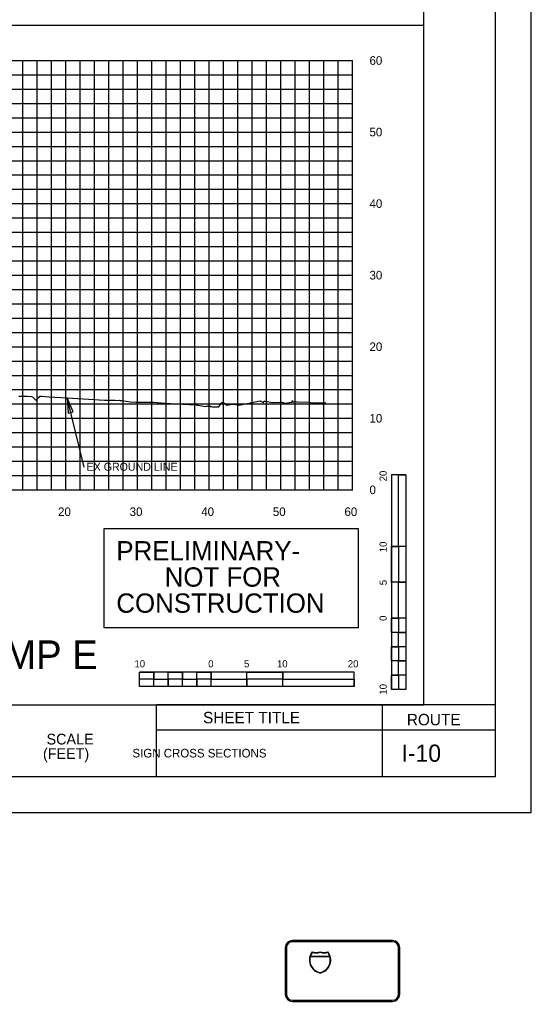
# Model space of a CAD drawing. Extents: x 1797809 to 2198143, y 249608 to 1237864.
# Drawn here: x 2195126.4 to 2195197.9, y 1237091.6 to 1237228.8 of the extents above; entities that cross this region are included whole.
import ezdxf

# ---------------------------------------------------------------- set-up
doc = ezdxf.new("R2010")
doc.units = 0
for name, color, linetype in [('10', 7, 'Continuous'), ('29', 7, 'Continuous'), ('3', 7, 'Continuous'), ('31', 7, 'Continuous'), ('60', 7, 'Continuous'), ('DESIGN - SHEET - Light Grid', 7, 'Continuous'), ('GSCOLORFILL', 7, 'Continuous'), ('GSDIMS', 7, 'Continuous'), ('GSOUTLINE', 7, 'Continuous'), ('GSSHT', 7, 'Continuous'), ('Level 1', 7, 'Continuous'), ('Level 30', 7, 'Continuous'), ('Level 33', 7, 'Continuous'), ('Level 45', 7, 'Continuous'), ('Level 55', 7, 'Continuous'), ('UGUT', 7, 'Continuous')]:
    doc.layers.add(name, color=color, linetype=linetype)

msp = doc.modelspace()

# ---------------------------------------------------------------- linework, layer by layer
at = {"layer": '29'}
for p, q in [((2195178.33, 1237165.19), (2195178.33, 1237135.19)), ((2195180.33, 1237165.19), (2195178.33, 1237165.19)), ((2195178.33, 1237165.19), (2195178.33, 1237135.19)), ((2195180.33, 1237165.19), (2195178.33, 1237165.19)), ((2195180.33, 1237165.19), (2195180.33, 1237155.19)), ((2195180.33, 1237165.19), (2195180.33, 1237135.19)), ((2195180.33, 1237165.19), (2195180.33, 1237155.19)), ((2195180.33, 1237165.19), (2195180.33, 1237135.19)), ((2195179.33, 1237155.19), (2195178.33, 1237155.19)), ((2195180.33, 1237155.19), (2195178.33, 1237155.19)), ((2195179.33, 1237155.19), (2195178.33, 1237155.19)), ((2195180.33, 1237155.19), (2195178.33, 1237155.19)), ((2195179.33, 1237155.19), (2195179.33, 1237150.19)), ((2195179.33, 1237155.19), (2195179.33, 1237150.19)), ((2195180.33, 1237150.19), (2195178.33, 1237150.19)), ((2195180.33, 1237150.19), (2195178.33, 1237150.19)), ((2195180.33, 1237150.19), (2195179.33, 1237150.19)), ((2195180.33, 1237150.19), (2195179.33, 1237150.19)), ((2195180.33, 1237150.19), (2195180.33, 1237145.19)), ((2195180.33, 1237150.19), (2195180.33, 1237145.19)), ((2195179.33, 1237145.19), (2195178.33, 1237145.19)), ((2195180.33, 1237145.19), (2195178.33, 1237145.19)), ((2195179.33, 1237145.19), (2195178.33, 1237145.19)), ((2195180.33, 1237145.19), (2195178.33, 1237145.19)), ((2195179.33, 1237145.19), (2195179.33, 1237143.19)), ((2195179.33, 1237145.19), (2195179.33, 1237143.19)), ((2195180.33, 1237143.19), (2195179.33, 1237143.19)), ((2195180.33, 1237143.19), (2195179.33, 1237143.19)), ((2195180.33, 1237143.19), (2195180.33, 1237141.19)), ((2195180.33, 1237143.19), (2195180.33, 1237141.19)), ((2195179.33, 1237141.19), (2195178.33, 1237141.19)), ((2195179.33, 1237141.19), (2195178.33, 1237141.19)), ((2195179.33, 1237141.19), (2195179.33, 1237139.19)), ((2195179.33, 1237141.19), (2195179.33, 1237139.19)), ((2195180.33, 1237139.19), (2195179.33, 1237139.19)), ((2195180.33, 1237139.19), (2195179.33, 1237139.19)), ((2195180.33, 1237139.19), (2195180.33, 1237137.19)), ((2195180.33, 1237139.19), (2195180.33, 1237137.19)), ((2195173.13, 1237137.63), (2195143.13, 1237137.63)), ((2195143.13, 1237135.63), (2195143.13, 1237137.63)), ((2195173.13, 1237137.63), (2195143.13, 1237137.63)), ((2195143.13, 1237135.63), (2195143.13, 1237137.63)), ((2195145.13, 1237136.63), (2195145.13, 1237137.63)), ((2195145.13, 1237136.63), (2195145.13, 1237137.63)), ((2195149.13, 1237136.63), (2195149.13, 1237137.63)), ((2195149.13, 1237136.63), (2195149.13, 1237137.63)), ((2195153.13, 1237136.63), (2195153.13, 1237137.63)), ((2195153.13, 1237135.63), (2195153.13, 1237137.63)), ((2195153.13, 1237136.63), (2195153.13, 1237137.63)), ((2195153.13, 1237135.63), (2195153.13, 1237137.63)), ((2195158.13, 1237135.63), (2195158.13, 1237137.63)), ((2195158.13, 1237135.63), (2195158.13, 1237137.63)), ((2195163.13, 1237136.63), (2195163.13, 1237137.63)), ((2195163.13, 1237135.63), (2195163.13, 1237137.63)), ((2195163.13, 1237136.63), (2195163.13, 1237137.63)), ((2195163.13, 1237135.63), (2195163.13, 1237137.63)), ((2195173.13, 1237135.63), (2195173.13, 1237137.63)), ((2195173.13, 1237135.63), (2195173.13, 1237137.63)), ((2195145.13, 1237136.63), (2195143.13, 1237136.63)), ((2195145.13, 1237136.63), (2195143.13, 1237136.63)), ((2195147.13, 1237135.63), (2195147.13, 1237136.63)), ((2195149.13, 1237136.63), (2195147.13, 1237136.63)), ((2195147.13, 1237135.63), (2195147.13, 1237136.63)), ((2195149.13, 1237136.63), (2195147.13, 1237136.63)), ((2195151.13, 1237135.63), (2195151.13, 1237136.63)), ((2195153.13, 1237136.63), (2195151.13, 1237136.63)), ((2195151.13, 1237135.63), (2195151.13, 1237136.63)), ((2195153.13, 1237136.63), (2195151.13, 1237136.63)), ((2195158.13, 1237135.63), (2195158.13, 1237136.63)), ((2195163.13, 1237136.63), (2195158.13, 1237136.63)), ((2195158.13, 1237135.63), (2195158.13, 1237136.63)), ((2195163.13, 1237136.63), (2195158.13, 1237136.63)), ((2195179.33, 1237137.19), (2195178.33, 1237137.19)), ((2195179.33, 1237137.19), (2195178.33, 1237137.19)), ((2195179.33, 1237137.19), (2195179.33, 1237135.19)), ((2195179.33, 1237137.19), (2195179.33, 1237135.19)), ((2195173.13, 1237135.63), (2195143.13, 1237135.63)), ((2195173.13, 1237135.63), (2195143.13, 1237135.63)), ((2195147.13, 1237135.63), (2195145.13, 1237135.63)), ((2195147.13, 1237135.63), (2195145.13, 1237135.63)), ((2195151.13, 1237135.63), (2195149.13, 1237135.63)), ((2195151.13, 1237135.63), (2195149.13, 1237135.63)), ((2195158.13, 1237135.63), (2195153.13, 1237135.63)), ((2195158.13, 1237135.63), (2195153.13, 1237135.63)), ((2195173.13, 1237135.63), (2195163.13, 1237135.63)), ((2195173.13, 1237135.63), (2195163.13, 1237135.63)), ((2195180.33, 1237135.19), (2195178.33, 1237135.19)), ((2195180.33, 1237135.19), (2195178.33, 1237135.19))]:
    msp.add_line(p, q, dxfattribs=at)
for points in [[(2195179.33, 1237155.19), (2195179.33, 1237165.19), (2195180.33, 1237165.19), (2195180.33, 1237155.19)], [(2195179.33, 1237155.19), (2195179.33, 1237165.19), (2195180.33, 1237165.19), (2195180.33, 1237155.19)], [(2195178.33, 1237150.19), (2195178.33, 1237155.19), (2195179.33, 1237155.19), (2195179.33, 1237150.19)], [(2195178.33, 1237150.19), (2195178.33, 1237155.19), (2195179.33, 1237155.19), (2195179.33, 1237150.19)], [(2195179.33, 1237145.19), (2195179.33, 1237150.19), (2195180.33, 1237150.19), (2195180.33, 1237145.19)], [(2195179.33, 1237145.19), (2195179.33, 1237150.19), (2195180.33, 1237150.19), (2195180.33, 1237145.19)], [(2195178.33, 1237143.19), (2195178.33, 1237145.19), (2195179.33, 1237145.19), (2195179.33, 1237143.19)], [(2195178.33, 1237143.19), (2195178.33, 1237145.19), (2195179.33, 1237145.19), (2195179.33, 1237143.19)], [(2195179.33, 1237141.19), (2195179.33, 1237143.19), (2195180.33, 1237143.19), (2195180.33, 1237141.19)], [(2195179.33, 1237141.19), (2195179.33, 1237143.19), (2195180.33, 1237143.19), (2195180.33, 1237141.19)], [(2195178.33, 1237139.19), (2195178.33, 1237141.19), (2195179.33, 1237141.19), (2195179.33, 1237139.19)], [(2195178.33, 1237139.19), (2195178.33, 1237141.19), (2195179.33, 1237141.19), (2195179.33, 1237139.19)], [(2195179.33, 1237137.19), (2195179.33, 1237139.19), (2195180.33, 1237139.19), (2195180.33, 1237137.19)], [(2195179.33, 1237137.19), (2195179.33, 1237139.19), (2195180.33, 1237139.19), (2195180.33, 1237137.19)], [(2195143.13, 1237137.63), (2195145.13, 1237137.63), (2195145.13, 1237136.63), (2195143.13, 1237136.63)], [(2195143.13, 1237137.63), (2195145.13, 1237137.63), (2195145.13, 1237136.63), (2195143.13, 1237136.63)], [(2195147.13, 1237137.63), (2195149.13, 1237137.63), (2195149.13, 1237136.63), (2195147.13, 1237136.63)], [(2195147.13, 1237137.63), (2195149.13, 1237137.63), (2195149.13, 1237136.63), (2195147.13, 1237136.63)], [(2195151.13, 1237137.63), (2195153.13, 1237137.63), (2195153.13, 1237136.63), (2195151.13, 1237136.63)], [(2195151.13, 1237137.63), (2195153.13, 1237137.63), (2195153.13, 1237136.63), (2195151.13, 1237136.63)], [(2195158.13, 1237137.63), (2195163.13, 1237137.63), (2195163.13, 1237136.63), (2195158.13, 1237136.63)], [(2195158.13, 1237137.63), (2195163.13, 1237137.63), (2195163.13, 1237136.63), (2195158.13, 1237136.63)], [(2195145.13, 1237136.63), (2195147.13, 1237136.63), (2195147.13, 1237135.63), (2195145.13, 1237135.63)], [(2195145.13, 1237136.63), (2195147.13, 1237136.63), (2195147.13, 1237135.63), (2195145.13, 1237135.63)], [(2195149.13, 1237136.63), (2195151.13, 1237136.63), (2195151.13, 1237135.63), (2195149.13, 1237135.63)], [(2195149.13, 1237136.63), (2195151.13, 1237136.63), (2195151.13, 1237135.63), (2195149.13, 1237135.63)], [(2195153.13, 1237136.63), (2195158.13, 1237136.63), (2195158.13, 1237135.63), (2195153.13, 1237135.63)], [(2195153.13, 1237136.63), (2195158.13, 1237136.63), (2195158.13, 1237135.63), (2195153.13, 1237135.63)], [(2195163.13, 1237136.63), (2195173.13, 1237136.63), (2195173.13, 1237135.63), (2195163.13, 1237135.63)], [(2195163.13, 1237136.63), (2195173.13, 1237136.63), (2195173.13, 1237135.63), (2195163.13, 1237135.63)], [(2195178.33, 1237135.19), (2195178.33, 1237137.19), (2195179.33, 1237137.19), (2195179.33, 1237135.19)], [(2195178.33, 1237135.19), (2195178.33, 1237137.19), (2195179.33, 1237137.19), (2195179.33, 1237135.19)]]:
    msp.add_lwpolyline(points, close=True, dxfattribs=at)
at = {"layer": '3'}
for p, q in [((2194882.86, 1237228.05), (2195182.86, 1237228.05)), ((2195135.41, 1237166.27), (2195133.01, 1237175.96))]:
    msp.add_line(p, q, dxfattribs=at)
at = {"layer": '60'}
for p, q in [((2195172.86, 1237163.11), (2195172.86, 1237223.11)), ((2195172.92, 1237203.11), (2195172.86, 1237203.11)), ((2195172.92, 1237193.11), (2195172.86, 1237193.11)), ((2195172.92, 1237183.11), (2195172.86, 1237183.11)), ((2195172.92, 1237173.11), (2195172.86, 1237173.11)), ((2195042.86, 1237163.11), (2195172.86, 1237163.11)), ((2195132.86, 1237163.05), (2195132.86, 1237163.11)), ((2195142.86, 1237163.05), (2195142.86, 1237163.11)), ((2195152.86, 1237163.05), (2195152.86, 1237163.11)), ((2195162.86, 1237163.05), (2195162.86, 1237163.11)), ((2195172.86, 1237163.05), (2195172.86, 1237163.11)), ((2195172.92, 1237163.11), (2195172.86, 1237163.11))]:
    msp.add_line(p, q, dxfattribs=at)
at = {"layer": 'DESIGN - SHEET - Light Grid'}
msp.add_lwpolyline([(2195126.28, 1237176.21), (2195126.62, 1237176.21), (2195127.09, 1237176.21), (2195127.33, 1237176.21), (2195127.45, 1237176.21), (2195128.07, 1237176.14), (2195128.17, 1237176.09), (2195128.27, 1237176.03), (2195128.58, 1237175.72), (2195128.62, 1237175.71), (2195128.72, 1237175.64), (2195129.14, 1237176.06), (2195129.23, 1237176.21), (2195129.43, 1237176.21), (2195130.49, 1237176.12), (2195133.01, 1237175.96), (2195138.24, 1237175.63), (2195139.73, 1237175.64), (2195140.21, 1237175.61), (2195140.34, 1237175.63), (2195140.42, 1237175.6), (2195140.68, 1237175.61), (2195141.9, 1237175.42), (2195142.61, 1237175.38), (2195144.95, 1237175.38), (2195145.08, 1237175.38), (2195146.11, 1237175.26), (2195148.21, 1237175.13), (2195151.01, 1237174.97), (2195152.39, 1237174.77), (2195152.64, 1237174.87), (2195152.66, 1237174.78), (2195152.91, 1237174.82), (2195152.93, 1237174.91), (2195152.99, 1237174.78), (2195153, 1237174.77), (2195153.02, 1237174.75), (2195153.07, 1237174.76), (2195153.21, 1237174.75), (2195153.31, 1237174.73), (2195153.59, 1237174.71), (2195153.95, 1237174.69), (2195154.21, 1237174.71), (2195154.23, 1237174.72), (2195154.52, 1237175.22), (2195154.72, 1237175.38), (2195154.76, 1237175.17), (2195154.8, 1237175.34), (2195155.34, 1237174.94), (2195155.41, 1237174.96), (2195155.5, 1237174.99), (2195155.8, 1237175.03), (2195156.34, 1237175.07), (2195157.02, 1237174.92), (2195159.99, 1237175.57), (2195160.47, 1237175.3), (2195160.52, 1237175.44), (2195160.59, 1237175.49), (2195160.7, 1237175.51), (2195161.77, 1237175.32), (2195162.72, 1237175.38), (2195162.85, 1237175.37), (2195163.03, 1237175.34), (2195163.46, 1237175.24), (2195164.39, 1237175.35), (2195164.52, 1237175.58), (2195164.53, 1237175.4), (2195164.54, 1237175.34), (2195164.91, 1237175.46), (2195165.06, 1237175.41), (2195166.86, 1237175.37), (2195167.27, 1237175.27), (2195169.17, 1237175.26)], dxfattribs=at)
at = {"layer": 'GSCOLORFILL'}
for p, q in [((2195145.52, 1237123.04), (2195145.52, 1237133.05)), ((2195177.05, 1237123.04), (2195177.05, 1237133.05))]:
    msp.add_line(p, q, dxfattribs=at)
msp.add_lwpolyline([(2194870.36, 1237123.04), (2195192.86, 1237123.04), (2195192.86, 1237333.04), (2194870.36, 1237333.04)], close=True, dxfattribs=at)
at = {"layer": 'GSDIMS'}
msp.add_lwpolyline([(2195133.01, 1237175.96), (2195133.18, 1237173.82), (2195133.86, 1237174.01)], close=True, dxfattribs=at)
at = {"layer": 'GSOUTLINE'}
for p, q in [((2195145.52, 1237129.57), (2195177.05, 1237129.57)), ((2195177.05, 1237129.57), (2195192.86, 1237129.57)), ((2195163.49, 1237099.12), (2195163.49, 1237092.62)), ((2195163.65, 1237099.12), (2195163.65, 1237092.62)), ((2195178.48, 1237100.12), (2195164.49, 1237100.12)), ((2195178.48, 1237099.95), (2195164.49, 1237099.95)), ((2195179.32, 1237092.62), (2195179.32, 1237099.12)), ((2195179.48, 1237092.62), (2195179.48, 1237099.12)), ((2195164.49, 1237091.79), (2195178.48, 1237091.79)), ((2195164.49, 1237091.62), (2195178.48, 1237091.62))]:
    msp.add_line(p, q, dxfattribs=at)
for points in [[(2195169.73, 1237097.87), (2195166.99, 1237097.87)], [(2195167, 1237097.93), (2195169.71, 1237097.93)]]:
    msp.add_lwpolyline(points, dxfattribs=at)
for centre, major_axis, ratio, start_param, end_param in [((2195164.49, 1237099.12), (1, 0), 0.999829, 1.570796, 3.141593), ((2195164.49, 1237099.12), (0.833, 0), 0.999829, 1.570796, 3.141593), ((2195178.48, 1237099.12), (1, 0), 0.999829, 0, 1.570796), ((2195178.48, 1237099.12), (0.833, 0), 0.999829, 0, 1.570796), ((2195168.73, 1237097.4), (1.87, 0), 0.997059, 2.472588, 4.511032), ((2195168.73, 1237097.4), (1.81, 0), 0.997059, 2.876207, 4.503988), ((2195168.73, 1237097.4), (1.81, 0), 0.997059, 2.495747, 2.84029), ((2195167.81, 1237100.34), (1.87, 0), 0.997059, 4.415842, 5.008936), ((2195167.81, 1237100.34), (1.94, 0), 0.997059, 4.438241, 4.999094), ((2195168.91, 1237100.34), (1.87, 0), 0.997059, 4.415842, 5.008936), ((2195167.98, 1237097.4), (1.87, 0), 0.997059, 4.913746, 6.95219), ((2195168.91, 1237100.34), (1.94, 0), 0.997059, 4.425684, 4.986537), ((2195167.98, 1237097.4), (1.81, 0), 0.997059, 4.92079, 6.548571), ((2195167.98, 1237097.4), (1.81, 0), 0.997059, 0.301302, 0.645846), ((2195164.49, 1237092.62), (1, 0), 0.999829, 3.141593, 4.712389), ((2195164.49, 1237092.62), (0.833, 0), 0.999829, 3.141593, 4.712389), ((2195178.48, 1237092.62), (1, 0), 0.999829, 4.712389, 6.283185), ((2195178.48, 1237092.62), (0.833, 0), 0.999829, 4.712389, 6.283185)]:
    msp.add_ellipse(centre, major_axis=major_axis, ratio=ratio, start_param=start_param, end_param=end_param, dxfattribs=at)
at = {"layer": 'GSSHT'}
for p, q in [((2195042.86, 1237223.11), (2195172.86, 1237223.11)), ((2195126.86, 1237163.11), (2195126.86, 1237223.11)), ((2195128.86, 1237163.11), (2195128.86, 1237223.11)), ((2195130.86, 1237163.11), (2195130.86, 1237223.11)), ((2195132.86, 1237163.11), (2195132.86, 1237223.11)), ((2195134.86, 1237163.11), (2195134.86, 1237223.11)), ((2195136.86, 1237163.11), (2195136.86, 1237223.11)), ((2195138.86, 1237163.11), (2195138.86, 1237223.11)), ((2195140.86, 1237163.11), (2195140.86, 1237223.11)), ((2195142.86, 1237163.11), (2195142.86, 1237223.11)), ((2195144.86, 1237163.11), (2195144.86, 1237223.11)), ((2195146.86, 1237163.11), (2195146.86, 1237223.11)), ((2195148.86, 1237163.11), (2195148.86, 1237223.11)), ((2195150.86, 1237163.11), (2195150.86, 1237223.11)), ((2195152.86, 1237163.11), (2195152.86, 1237223.11)), ((2195154.86, 1237163.11), (2195154.86, 1237223.11)), ((2195156.86, 1237163.11), (2195156.86, 1237223.11)), ((2195158.86, 1237163.11), (2195158.86, 1237223.11)), ((2195160.86, 1237163.11), (2195160.86, 1237223.11)), ((2195162.86, 1237163.11), (2195162.86, 1237223.11)), ((2195164.86, 1237163.11), (2195164.86, 1237223.11)), ((2195166.86, 1237163.11), (2195166.86, 1237223.11)), ((2195168.86, 1237163.11), (2195168.86, 1237223.11)), ((2195170.86, 1237163.11), (2195170.86, 1237223.11)), ((2195172.86, 1237163.11), (2195172.86, 1237223.11)), ((2195042.86, 1237221.11), (2195172.86, 1237221.11)), ((2195042.86, 1237219.11), (2195172.86, 1237219.11)), ((2195042.86, 1237217.11), (2195172.86, 1237217.11)), ((2195042.86, 1237215.11), (2195172.86, 1237215.11)), ((2195042.86, 1237213.11), (2195172.86, 1237213.11)), ((2195042.86, 1237211.11), (2195172.86, 1237211.11)), ((2195042.86, 1237209.11), (2195172.86, 1237209.11)), ((2195042.86, 1237207.11), (2195172.86, 1237207.11)), ((2195042.86, 1237205.11), (2195172.86, 1237205.11)), ((2195042.86, 1237203.11), (2195172.86, 1237203.11)), ((2195042.86, 1237201.11), (2195172.86, 1237201.11)), ((2195042.86, 1237199.11), (2195172.86, 1237199.11)), ((2195042.86, 1237197.11), (2195172.86, 1237197.11)), ((2195042.86, 1237195.11), (2195172.86, 1237195.11)), ((2195042.86, 1237193.11), (2195172.86, 1237193.11)), ((2195042.86, 1237191.11), (2195172.86, 1237191.11)), ((2195042.86, 1237189.11), (2195172.86, 1237189.11)), ((2195042.86, 1237187.11), (2195172.86, 1237187.11)), ((2195042.86, 1237185.11), (2195172.86, 1237185.11)), ((2195042.86, 1237183.11), (2195172.86, 1237183.11)), ((2195042.86, 1237181.11), (2195172.86, 1237181.11)), ((2195042.86, 1237179.11), (2195172.86, 1237179.11)), ((2195042.86, 1237177.11), (2195172.86, 1237177.11)), ((2195042.86, 1237175.11), (2195172.86, 1237175.11)), ((2195042.86, 1237173.11), (2195172.86, 1237173.11)), ((2195042.86, 1237171.11), (2195172.86, 1237171.11)), ((2195042.86, 1237169.11), (2195172.86, 1237169.11)), ((2195042.86, 1237167.11), (2195172.86, 1237167.11)), ((2195042.86, 1237165.11), (2195172.86, 1237165.11)), ((2195042.86, 1237163.11), (2195172.86, 1237163.11))]:
    msp.add_line(p, q, dxfattribs=at)
msp.add_lwpolyline([(2194857.86, 1237118.04), (2195197.86, 1237118.04), (2195197.86, 1237338.04), (2194857.86, 1237338.04)], close=True, dxfattribs=at)
at = {"layer": 'Level 30'}
msp.add_lwpolyline([(2195138.22, 1237157.72), (2195173.68, 1237157.72), (2195173.68, 1237143.82), (2195138.22, 1237143.82)], close=True, dxfattribs=at)
at = {"layer": 'Level 45'}
msp.add_lwpolyline([(2194882.86, 1237133.05), (2195182.86, 1237133.05), (2195182.86, 1237323.05), (2194882.86, 1237323.05)], close=True, dxfattribs=at)
at = {"layer": 'UGUT'}
msp.add_line((2195192.86, 1237133.05), (2195145.52, 1237133.05), dxfattribs=at)

# ---------------------------------------------------------------- texts
at = {"layer": '10'}
for s, p in [('20', (2195131.76, 1237159.45)), ('30', (2195141.76, 1237159.45)), ('40', (2195151.76, 1237159.45)), ('50', (2195161.76, 1237159.45)), ('60', (2195171.76, 1237159.45))]:
    msp.add_text(s, height=1.2, dxfattribs=at).set_placement(p)
at = {"layer": '29'}
for s, height, rotation, p in [('20', 0.999, 90.0572, (2195177.66, 1237164.3)), ('20', 0.999, 90.0572, (2195177.66, 1237164.3)), ('10', 0.999, 90.0572, (2195177.66, 1237154.39)), ('10', 0.999, 90.0572, (2195177.66, 1237154.39)), ('5', 1, 90.0572, (2195177.66, 1237149.78)), ('5', 1, 90.0572, (2195177.66, 1237149.78)), ('0', 1, 90.0572, (2195177.66, 1237144.79)), ('0', 1, 90.0572, (2195177.66, 1237144.79)), ('10', 0.999, 0.0572, (2195142.43, 1237138.3)), ('10', 0.999, 0.0572, (2195142.43, 1237138.3)), ('0', 1, 0.0572, (2195152.73, 1237138.3)), ('0', 1, 0.0572, (2195152.73, 1237138.3)), ('5', 0.999, 0.0572, (2195157.73, 1237138.3)), ('5', 0.999, 0.0572, (2195157.73, 1237138.3)), ('10', 0.999, 0.0572, (2195162.33, 1237138.3)), ('10', 0.999, 0.0572, (2195162.33, 1237138.3)), ('20', 0.999, 0.0572, (2195172.23, 1237138.3)), ('20', 0.999, 0.0572, (2195172.23, 1237138.3)), ('10', 0.999, 90.0572, (2195177.66, 1237134.49)), ('10', 0.999, 90.0572, (2195177.66, 1237134.49))]:
    msp.add_text(s, height=height, rotation=rotation, dxfattribs=at).set_placement(p)
at = {"layer": '31'}
for s, p in [('60', (2195175.26, 1237222.51)), ('50', (2195175.26, 1237212.51)), ('40', (2195175.26, 1237202.51)), ('30', (2195175.26, 1237192.51)), ('20', (2195175.26, 1237182.51)), ('10', (2195175.26, 1237172.51)), ('0', (2195175.26, 1237162.51))]:
    msp.add_text(s, height=1.2, dxfattribs=at).set_placement(p)
at = {"layer": 'GSDIMS'}
for s, p in [('SCALE', (2195130.15, 1237127.52)), ('(FEET)', (2195129.65, 1237125.49))]:
    msp.add_text(s, height=1.499, rotation=0.0572, dxfattribs=at).set_placement(p)
at = {"layer": 'GSOUTLINE'}
for s, p in [('SHEET TITLE', (2195152.01, 1237130.48)), ('ROUTE', (2195180.48, 1237130.2))]:
    msp.add_text(s, height=1.6, dxfattribs=at).set_placement(p)
at = {"layer": 'Level 1'}
for s, height, p in [('          SIGN CROSS SECTIONS          ', 1.2, (2195137.69, 1237125.71)), (' I-10 ', 2.4, (2195178.83, 1237125.11))]:
    msp.add_text(s, height=height, rotation=360, dxfattribs=at).set_placement(p)
at = {"layer": 'Level 30'}
for s, p in [('PRELIMINARY-', (2195139.9, 1237153.24)), ('NOT FOR', (2195146.65, 1237149.58)), ('CONSTRUCTION', (2195139.9, 1237145.93))]:
    msp.add_text(s, height=2.7, dxfattribs=at).set_placement(p)
at = {"layer": 'Level 33'}
msp.add_text('RAMP E', height=3.998, rotation=360, dxfattribs=at).set_placement((2195116.81, 1237138.07))
at = {"layer": 'Level 55'}
msp.add_text('EX GROUND LINE', height=1.1105, dxfattribs=at).set_placement((2195135.74, 1237165.78))

doc.saveas('drawing.dxf')
